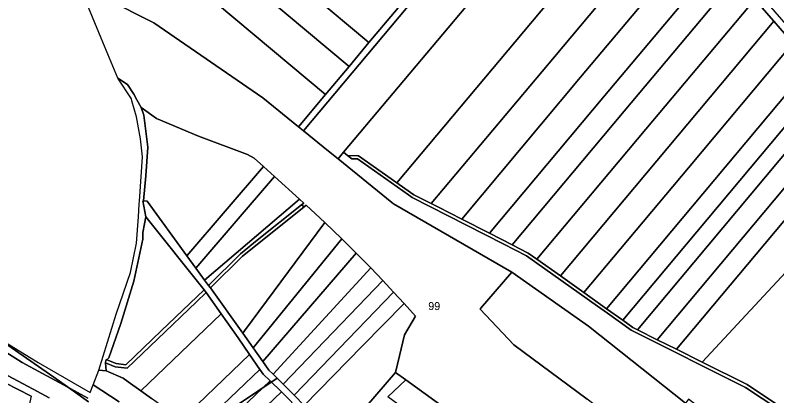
# Model space of a CAD drawing. Extents: x -545779 to -541342, y -1153413 to -1149956.
# Drawn here: x -544066.7 to -543590.9, y -1150988.9 to -1150751.1 of the extents above; entities that cross this region are included whole.
import ezdxf

# ---------------------------------------------------------------- set-up
doc = ezdxf.new("R2010")
doc.units = 0
for name, color, linetype in [('95560013', 7, 'Continuous'), ('95590013', 7, 'Continuous'), ('95620013', 7, 'Continuous'), ('95630013', 7, 'Continuous'), ('95640013', 7, 'Continuous'), ('95660013', 7, 'Continuous')]:
    doc.layers.add(name, color=color, linetype=linetype)

msp = doc.modelspace()

# ---------------------------------------------------------------- linework, layer by layer
at = {"layer": '95560013'}
for points in [[(-543827.47, -1150746.45), (-543845.7, -1150768.23), (-543993.28, -1150644.7), (-543977.98, -1150621.5), (-543977.39, -1150620.95)], [(-543801.78, -1150722.14), (-543716.9, -1150620.9), (-543711.61, -1150620.82), (-543695.42, -1150638.6), (-543778.48, -1150737.68), (-543861.53, -1150836.77), (-543865.01, -1150840.92), (-543870.95, -1150836.1), (-543886.65, -1150823.39)], [(-543749.03, -1150761.28), (-543828.26, -1150855.81), (-543852.23, -1150838.93), (-543859.01, -1150838.76), (-543861.53, -1150836.77), (-543778.48, -1150737.68), (-543695.42, -1150638.6), (-543669.78, -1150666.75)], [(-543858.13, -1150783.08), (-544004.01, -1150660.97), (-543993.28, -1150644.7), (-543845.7, -1150768.23)], [(-544020.45, -1150676.94), (-544018.78, -1150671.48), (-544015.88, -1150665.87), (-544009.5, -1150669.31), (-544004.01, -1150660.97), (-543858.13, -1150783.08), (-543872.76, -1150800.56)], [(-543817.68, -1150863.26), (-543819.79, -1150861.77), (-543828.26, -1150855.81), (-543749.03, -1150761.28), (-543669.78, -1150666.75), (-543652.94, -1150685.25), (-543729.87, -1150777.02), (-543806.8, -1150868.8)], [(-543980.18, -1150755.91), (-543984.63, -1150753.63), (-544024.7, -1150733.15), (-544026.25, -1150733.04), (-544026.37, -1150732.2), (-544027.19, -1150726.47), (-544028.18, -1150725.94), (-544028.6, -1150725.71), (-544029.66, -1150713.36), (-544030.04, -1150708.97), (-544030.08, -1150708.47), (-544020.45, -1150676.94), (-543872.76, -1150800.56), (-543889.76, -1150820.87), (-543912.05, -1150802.81)], [(-543639.09, -1150701.19), (-543713.46, -1150789.91), (-543787.73, -1150878.52), (-543802.3, -1150871.09), (-543806.8, -1150868.8), (-543729.87, -1150777.02), (-543652.94, -1150685.25)], [(-543626.57, -1150715.69), (-543698.51, -1150801.5), (-543770.45, -1150887.32), (-543787.73, -1150878.52), (-543713.46, -1150789.91), (-543639.09, -1150701.19)], [(-543770.45, -1150887.32), (-543698.51, -1150801.5), (-543626.57, -1150715.69), (-543616.26, -1150727.64), (-543686.23, -1150811.11), (-543756.2, -1150894.58)], [(-543740.79, -1150903.51), (-543746.15, -1150899.7), (-543756.2, -1150894.58), (-543686.23, -1150811.11), (-543616.26, -1150727.64), (-543604.66, -1150741.11), (-543672.72, -1150822.31)], [(-543672.72, -1150822.31), (-543604.66, -1150741.11), (-543592.73, -1150754.92), (-543659.4, -1150834.46), (-543726.08, -1150914), (-543740.79, -1150903.51)], [(-543580.88, -1150768.65), (-543646.17, -1150846.54), (-543711.46, -1150924.42), (-543726.08, -1150914), (-543659.4, -1150834.46), (-543592.73, -1150754.92)], [(-543711.46, -1150924.42), (-543646.17, -1150846.54), (-543580.88, -1150768.65), (-543569.46, -1150781.88), (-543697.36, -1150934.46)], [(-543697.36, -1150934.46), (-543569.46, -1150781.88), (-543561.26, -1150791.53), (-543687.16, -1150941.72)], [(-543554.2, -1150799.85), (-543678.05, -1150947.61), (-543680.89, -1150946.19), (-543687.16, -1150941.72), (-543561.26, -1150791.53)], [(-543678.05, -1150947.61), (-543554.2, -1150799.85), (-543545.33, -1150810.3), (-543665.64, -1150953.82)], [(-543984.21, -1150867.28), (-543986.65, -1150867.16), (-543985.06, -1150851.4), (-543983.8, -1150833.47), (-543986.33, -1150813.49), (-543987.95, -1150808.86), (-543978.35, -1150815.7), (-543952.16, -1150826.63), (-543921.63, -1150838.04), (-543917.39, -1150840.52), (-543911.64, -1150845.71), (-543959.5, -1150901.36)], [(-543536.8, -1150820.37), (-543653.68, -1150959.8), (-543665.64, -1150953.82), (-543545.33, -1150810.3)], [(-543637.45, -1150967.92), (-543653.68, -1150959.8), (-543536.8, -1150820.37), (-543519.45, -1150840.83)], [(-543830.4, -1150868.97), (-543831.46, -1150868.11), (-543865.01, -1150840.92), (-543861.53, -1150836.77), (-543859.01, -1150838.76), (-543856.39, -1150840.83), (-543852.89, -1150840.92), (-543821.09, -1150863.31), (-543818.71, -1150864.99), (-543761.92, -1150893.91), (-543747.19, -1150901.41), (-543702.88, -1150932.98), (-543696.76, -1150937.34), (-543681.92, -1150947.91), (-543610.53, -1150983.63), (-543558.5, -1151018.16), (-543584.15, -1151038.63), (-543646.06, -1150991.05), (-543647.89, -1150993.43), (-543708.46, -1150945.44), (-543756.47, -1150911.73)], [(-543609.52, -1150981.9), (-543637.45, -1150967.92), (-543519.45, -1150840.83), (-543470.44, -1150898.61), (-543581.82, -1151000.28)], [(-543904.7, -1150851.96), (-543953.87, -1150909.14), (-543959.5, -1150901.36), (-543911.64, -1150845.71)], [(-543904.7, -1150851.96), (-543889.18, -1150865.96), (-543948.46, -1150916.62), (-543953.87, -1150909.14)], [(-543889.18, -1150865.96), (-543886.4, -1150868.47), (-543887.76, -1150869.57), (-543915.55, -1150891.74), (-543926.01, -1150900.09), (-543946.01, -1150919.98), (-543948.46, -1150916.62)], [(-543924.67, -1150901.59), (-543918.69, -1150896.8), (-543886.25, -1150870.84), (-543884.94, -1150869.81), (-543873.19, -1150880.51), (-543923.54, -1150948.33), (-543924.53, -1150949.66), (-543944.64, -1150921.44)], [(-544003.69, -1150968.75), (-544009.35, -1150966.49), (-544008.29, -1150965.17), (-544000.69, -1150943.79), (-543992.6, -1150917.29), (-543987.06, -1150891.11), (-543986.89, -1150886.87), (-543985.95, -1150881.47), (-543985.16, -1150876.98), (-543948.6, -1150922.72), (-543975.44, -1150948.39), (-543997.5, -1150969.49)], [(-543755.27, -1150957.07), (-543776.22, -1150934.68), (-543776, -1150934.43), (-543756.47, -1150911.73), (-543708.46, -1150945.44), (-543647.89, -1150993.43), (-543583.74, -1151042.73), (-543583.69, -1151048), (-543596.49, -1151058.45), (-543608.97, -1151067.59), (-543670.14, -1151020.9), (-543709.38, -1150990.96)], [(-543996.04, -1150980.21), (-543999.31, -1150977.86), (-544009.79, -1150973.38), (-544010.23, -1150968.29), (-544004.18, -1150970.7), (-543996.79, -1150971.58), (-543977.89, -1150953.5), (-543953.47, -1150930.15), (-543947.35, -1150924.29), (-543937.96, -1150937.66), (-543988.28, -1150985.79)], [(-543826.66, -1150963.9), (-543829.21, -1150974.23), (-543853.73, -1151002.83), (-543861.11, -1151006.08), (-543870.82, -1151004.4), (-543886.12, -1150994.88), (-543849.65, -1150957.68), (-543823.76, -1150931.28), (-543816.58, -1150939.09), (-543823.42, -1150950.72)], [(-543974.85, -1150995.44), (-543981.64, -1150990.56), (-543988.28, -1150985.79), (-543937.96, -1150937.66), (-543927.4, -1150952.69), (-543920.24, -1150963.08), (-543963.71, -1151004.65), (-543968.38, -1151000.09)], [(-543961.11, -1151007.19), (-543963.71, -1151004.65), (-543920.24, -1150963.08), (-543913.78, -1150972.44), (-543955.68, -1151012.5)], [(-543907.44, -1150979.6), (-543948.83, -1151019.18), (-543955.68, -1151012.5), (-543913.78, -1150972.44), (-543911.77, -1150975.35)], [(-543948.83, -1151019.18), (-543907.44, -1150979.6), (-543900.43, -1150986.48), (-543941.84, -1151026.08)], [(-543833.82, -1150989.63), (-543822.74, -1150978.92), (-543748.74, -1151032.49), (-543757.51, -1151045.12), (-543762.58, -1151041.43), (-543780.39, -1151028.48), (-543798.2, -1151015.53), (-543816.01, -1151002.58)], [(-543893.74, -1150993.05), (-543935.26, -1151032.76), (-543941.84, -1151026.08), (-543900.43, -1150986.48)]]:
    msp.add_lwpolyline(points, close=True, dxfattribs=at)
at = {"layer": '95590013'}
msp.add_lwpolyline([(-544056.62, -1150989.15), (-544073.49, -1151065.25), (-544089.31, -1151058.21), (-544072.88, -1150980.84)], close=True, dxfattribs=at)
at = {"layer": '95620013'}
for points in [[(-543873.19, -1150880.51), (-543862.68, -1150890.87), (-543917.99, -1150958.92), (-543924.53, -1150949.66), (-543923.54, -1150948.33)], [(-543911.9, -1150967.55), (-543917.99, -1150958.92), (-543862.68, -1150890.87), (-543853.71, -1150899.71)], [(-543844.45, -1150908.84), (-543905.56, -1150975.43), (-543908.2, -1150972.79), (-543911.9, -1150967.55), (-543853.71, -1150899.71)], [(-543905.56, -1150975.43), (-543844.45, -1150908.84), (-543837.13, -1150916.75), (-543899.32, -1150981.67)], [(-543899.32, -1150981.67), (-543837.13, -1150916.75), (-543830.39, -1150924.08), (-543892.41, -1150988.59)], [(-543830.39, -1150924.08), (-543823.76, -1150931.28), (-543849.65, -1150957.68), (-543886.12, -1150994.88), (-543892.41, -1150988.59)]]:
    msp.add_lwpolyline(points, close=True, dxfattribs=at)
at = {"layer": '95630013'}
msp.add_lwpolyline([(-543988.85, -1150864.27), (-543987.15, -1150839.52), (-543988.46, -1150828.29), (-543990.46, -1150816.88), (-543990.87, -1150814.52), (-543993.76, -1150804.51), (-543994.07, -1150803.43), (-544002.61, -1150790.35), (-543996.47, -1150794.31), (-543992.64, -1150800.45), (-543990.71, -1150803.91), (-543987.95, -1150808.86), (-543986.33, -1150813.49), (-543983.8, -1150833.47), (-543985.06, -1150851.4), (-543986.65, -1150867.16), (-543987.01, -1150867.14), (-543985.16, -1150876.98), (-543985.95, -1150881.47), (-543986.89, -1150886.87), (-543987.06, -1150891.11), (-543992.6, -1150917.29), (-544000.69, -1150943.79), (-544008.29, -1150965.17), (-544009.35, -1150966.49), (-544009.85, -1150966.29), (-544010.26, -1150967.9), (-544010.23, -1150968.29), (-544009.79, -1150973.38), (-544014.52, -1150972.79), (-544003.52, -1150937.98), (-543994.59, -1150911.93), (-543990.85, -1150893.43), (-543989.72, -1150877.02), (-543989.19, -1150869.19), (-543989.04, -1150867.04)], close=True, dxfattribs=at)
for points in [[(-544119.43, -1150926.78), (-544052.4, -1150968.07), (-544019.95, -1150986.86), (-544018.08, -1150982.01), (-544001.77, -1150992.57)], [(-544021.34, -1150990.47), (-544034.19, -1150983.38), (-544062.24, -1150968.12), (-544084.54, -1150954.05)]]:
    msp.add_lwpolyline(points, dxfattribs=at)
at = {"layer": '95640013'}
for points in [[(-543756.11, -1150661.2), (-543713.01, -1150609.72), (-543709.83, -1150612.64), (-543716.9, -1150620.9), (-543801.78, -1150722.14), (-543886.65, -1150823.39), (-543889.76, -1150820.87), (-543872.76, -1150800.56), (-543858.13, -1150783.08), (-543845.7, -1150768.23), (-543827.47, -1150746.45), (-543809.16, -1150724.58), (-543787.12, -1150698.24), (-543761.24, -1150667.33)], [(-543924.67, -1150901.59), (-543944.64, -1150921.44), (-543946.01, -1150919.98), (-543926.01, -1150900.09), (-543915.55, -1150891.74), (-543887.76, -1150869.57), (-543886.25, -1150870.84), (-543918.69, -1150896.8)], [(-544004.18, -1150970.7), (-544010.23, -1150968.29), (-544010.26, -1150967.9), (-544009.85, -1150966.29), (-544009.35, -1150966.49), (-544003.69, -1150968.75), (-543997.5, -1150969.49), (-543975.44, -1150948.39), (-543948.6, -1150922.72), (-543947.35, -1150924.29), (-543953.47, -1150930.15), (-543977.89, -1150953.5), (-543996.79, -1150971.58)]]:
    msp.add_lwpolyline(points, close=True, dxfattribs=at)
for points in [[(-543648.32, -1150684.08), (-543561.88, -1150783.67), (-543475.45, -1150883.26), (-543438.36, -1150927.01), (-543438.05, -1150927.38), (-543437.53, -1150927.99), (-543445.92, -1150934.89), (-543445.28, -1150928.5), (-543446.48, -1150926.86), (-543470.44, -1150898.61), (-543519.45, -1150840.83), (-543536.8, -1150820.37), (-543545.33, -1150810.3), (-543554.2, -1150799.85), (-543561.26, -1150791.53), (-543569.46, -1150781.88), (-543580.88, -1150768.65), (-543592.73, -1150754.92), (-543604.66, -1150741.11)], [(-543748.74, -1151032.49), (-543822.74, -1150978.92), (-543829.21, -1150974.23), (-543826.66, -1150963.9), (-543823.42, -1150950.72), (-543816.58, -1150939.09), (-543823.76, -1150931.28), (-543830.39, -1150924.08), (-543837.13, -1150916.75), (-543844.45, -1150908.84), (-543853.71, -1150899.71), (-543862.68, -1150890.87), (-543873.19, -1150880.51), (-543884.94, -1150869.81), (-543886.25, -1150870.84), (-543887.76, -1150869.57), (-543886.4, -1150868.47), (-543889.18, -1150865.96), (-543904.7, -1150851.96), (-543911.64, -1150845.71), (-543917.39, -1150840.52), (-543921.63, -1150838.04), (-543952.16, -1150826.63), (-543978.35, -1150815.7), (-543987.95, -1150808.86), (-543990.71, -1150803.91), (-543992.64, -1150800.45), (-543996.47, -1150794.31), (-544002.61, -1150790.35), (-544005.66, -1150782.96), (-544012.92, -1150765.35), (-544026.25, -1150733.04)], [(-544024.7, -1150733.15), (-543984.63, -1150753.63), (-543980.18, -1150755.91), (-543912.05, -1150802.81), (-543889.76, -1150820.87), (-543886.65, -1150823.39), (-543870.95, -1150836.1), (-543865.01, -1150840.92), (-543831.46, -1150868.11), (-543830.4, -1150868.97), (-543756.47, -1150911.73), (-543776, -1150934.43), (-543776.22, -1150934.68), (-543755.27, -1150957.07), (-543709.38, -1150990.96)], [(-543558.5, -1151018.16), (-543610.53, -1150983.63), (-543681.92, -1150947.91), (-543696.76, -1150937.34), (-543702.88, -1150932.98), (-543747.19, -1150901.41), (-543761.92, -1150893.91), (-543818.71, -1150864.99), (-543821.09, -1150863.31), (-543852.89, -1150840.92), (-543856.39, -1150840.83), (-543859.01, -1150838.76), (-543852.23, -1150838.93), (-543828.26, -1150855.81), (-543819.79, -1150861.77), (-543817.68, -1150863.26), (-543806.8, -1150868.8), (-543802.3, -1150871.09), (-543787.73, -1150878.52), (-543770.45, -1150887.32), (-543756.2, -1150894.58), (-543746.15, -1150899.7), (-543740.79, -1150903.51), (-543726.08, -1150914), (-543711.46, -1150924.42), (-543697.36, -1150934.46), (-543687.16, -1150941.72), (-543680.89, -1150946.19), (-543678.05, -1150947.61), (-543665.64, -1150953.82), (-543653.68, -1150959.8), (-543637.45, -1150967.92), (-543609.52, -1150981.9), (-543581.82, -1151000.28)], [(-543893.74, -1150993.05), (-543900.43, -1150986.48), (-543907.44, -1150979.6), (-543911.77, -1150975.35), (-543913.78, -1150972.44), (-543920.24, -1150963.08), (-543927.4, -1150952.69), (-543937.96, -1150937.66), (-543947.35, -1150924.29), (-543948.6, -1150922.72), (-543985.16, -1150876.98), (-543987.01, -1150867.14), (-543986.65, -1150867.16), (-543984.21, -1150867.28), (-543959.5, -1150901.36), (-543953.87, -1150909.14), (-543948.46, -1150916.62), (-543946.01, -1150919.98), (-543944.64, -1150921.44), (-543924.53, -1150949.66), (-543917.99, -1150958.92), (-543911.9, -1150967.55), (-543908.2, -1150972.79), (-543905.56, -1150975.43), (-543899.32, -1150981.67), (-543892.41, -1150988.59), (-543886.12, -1150994.88)], [(-544084.54, -1150954.05), (-544062.24, -1150968.12), (-544034.19, -1150983.38), (-544021.34, -1150990.47)], [(-544001.77, -1150992.57), (-544018.08, -1150982.01), (-544014.52, -1150972.79), (-544009.79, -1150973.38), (-543999.31, -1150977.86), (-543996.04, -1150980.21), (-543988.28, -1150985.79), (-543981.64, -1150990.56)], [(-544045.54, -1150990.22), (-544055.56, -1150984.77), (-544071.41, -1150976.11)], [(-544071.41, -1150976.11), (-544055.56, -1150984.77), (-544045.54, -1150990.22)], [(-543853.73, -1151002.83), (-543829.21, -1150974.23), (-543822.74, -1150978.92), (-543833.82, -1150989.63)], [(-544056.62, -1150989.15), (-544072.88, -1150980.84)]]:
    msp.add_lwpolyline(points, dxfattribs=at)
at = {"layer": '95660013'}
for points in [[(-543748.74, -1151032.49), (-543822.74, -1150978.92), (-543829.21, -1150974.23), (-543826.66, -1150963.9), (-543823.42, -1150950.72), (-543816.58, -1150939.09), (-543823.76, -1150931.28), (-543849.65, -1150957.68), (-543886.12, -1150994.88), (-543892.41, -1150988.59), (-543899.32, -1150981.67), (-543903.114, -1150977.876), (-543905.56, -1150975.43), (-543908.2, -1150972.79), (-543911.9, -1150967.55), (-543917.99, -1150958.92), (-543924.53, -1150949.66), (-543923.54, -1150948.33), (-543873.19, -1150880.51), (-543884.94, -1150869.81), (-543886.25, -1150870.84), (-543887.76, -1150869.57), (-543886.4, -1150868.47), (-543889.18, -1150865.96), (-543904.7, -1150851.96), (-543911.64, -1150845.71), (-543917.39, -1150840.52), (-543921.63, -1150838.04), (-543952.16, -1150826.63), (-543978.35, -1150815.7), (-543987.95, -1150808.86), (-543990.71, -1150803.91), (-543992.64, -1150800.45), (-543996.47, -1150794.31), (-544002.61, -1150790.35), (-544005.66, -1150782.96), (-544012.92, -1150765.35), (-544026.25, -1150733.04)], [(-543590.84, -1151170.626), (-543596.525, -1151169.769), (-543607.02, -1151153.49), (-543634.9, -1151097.4), (-543638.05, -1151091.07), (-543608.97, -1151067.59), (-543670.14, -1151020.9), (-543709.38, -1150990.96), (-543755.27, -1150957.07), (-543776.22, -1150934.68), (-543776, -1150934.43), (-543756.47, -1150911.73), (-543830.4, -1150868.97), (-543831.46, -1150868.11), (-543865.01, -1150840.92), (-543870.95, -1150836.1), (-543886.65, -1150823.39), (-543889.76, -1150820.87), (-543912.05, -1150802.81), (-543980.18, -1150755.91), (-543984.63, -1150753.63), (-544024.7, -1150733.15)], [(-544024.7, -1150733.15), (-543984.63, -1150753.63), (-543980.18, -1150755.91), (-543912.05, -1150802.81), (-543889.76, -1150820.87), (-543886.65, -1150823.39), (-543870.95, -1150836.1), (-543865.01, -1150840.92), (-543831.46, -1150868.11), (-543830.4, -1150868.97), (-543756.47, -1150911.73), (-543776, -1150934.43), (-543776.22, -1150934.68), (-543755.27, -1150957.07), (-543709.38, -1150990.96)], [(-544119.43, -1150926.78), (-544052.4, -1150968.07), (-544019.95, -1150986.86), (-544018.08, -1150982.01), (-544014.52, -1150972.79), (-544003.52, -1150937.98), (-543994.59, -1150911.93), (-543990.85, -1150893.43), (-543989.72, -1150877.02), (-543989.19, -1150869.19), (-543989.04, -1150867.04), (-543988.85, -1150864.27), (-543987.15, -1150839.52), (-543988.46, -1150828.29), (-543990.46, -1150816.88), (-543990.87, -1150814.52), (-543993.76, -1150804.51), (-543994.07, -1150803.43), (-544002.61, -1150790.35), (-543996.47, -1150794.31), (-543992.64, -1150800.45), (-543990.71, -1150803.91), (-543987.95, -1150808.86), (-543978.35, -1150815.7), (-543952.16, -1150826.63), (-543921.63, -1150838.04), (-543917.39, -1150840.52), (-543911.64, -1150845.71), (-543904.7, -1150851.96), (-543889.18, -1150865.96), (-543886.4, -1150868.47), (-543887.76, -1150869.57), (-543886.25, -1150870.84), (-543884.94, -1150869.81), (-543873.19, -1150880.51), (-543923.54, -1150948.33), (-543924.53, -1150949.66), (-543917.99, -1150958.92), (-543911.9, -1150967.55), (-543908.2, -1150972.79), (-543905.56, -1150975.43), (-543903.114, -1150977.876), (-543939.178, -1151002.198)], [(-543939.178, -1151002.198), (-543903.114, -1150977.876), (-543899.32, -1150981.67), (-543892.41, -1150988.59), (-543886.12, -1150994.88), (-543849.65, -1150957.68), (-543823.76, -1150931.28), (-543816.58, -1150939.09), (-543823.42, -1150950.72), (-543826.66, -1150963.9), (-543829.21, -1150974.23), (-543822.74, -1150978.92), (-543748.74, -1151032.49)], [(-544079.025, -1150952.149), (-544042.531, -1150977.317), (-544030.47, -1150985.831), (-544020.84, -1150992.628)], [(-544020.84, -1150992.628), (-544030.47, -1150985.831), (-544042.531, -1150977.317), (-544079.025, -1150952.149)]]:
    msp.add_lwpolyline(points, dxfattribs=at)

# ---------------------------------------------------------------- texts
msp.add_text('99', height=5, rotation=360, dxfattribs=at).set_placement((-543808.655, -1150935.332))

doc.saveas('drawing.dxf')
